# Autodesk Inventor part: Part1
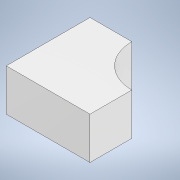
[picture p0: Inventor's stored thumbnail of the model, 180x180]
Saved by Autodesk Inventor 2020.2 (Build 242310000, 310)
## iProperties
Created: 2020-01
Part Number: Part1
Material: PBT Plastic
Document SubType Name: Modeling
Designer: thira
Density: 1.31 g/cm^3
Appearance: Smooth - White
Author: thira
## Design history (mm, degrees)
sketch "Sketch1"
  geometry: L1 (0, 0)-(0, -20); L2 (0, -20)-(-10, -20); L3 (-20, -10)-(-20, 0); L4 (0, 0)-(-20, 0); A1 r 10 centre (-20, -20) between (-10, -20) and (-20, -10)
  constraints: 8 end point, 2 horizontal, 2 perpendicular, 2 point on circle, 1 centre point, 1 point on line, 1 vertical
  dimensions: "d0" = 20 distance of L1.start L1.end; "d1" = 10 distance of L1.end L2.end; "d3" = 20 distance of L1.start L3.end
extrude "Extrusion1" new body sketch "Sketch1" distance "d4" = 10; taper "d5" = 0 deg
body "Solid1"
